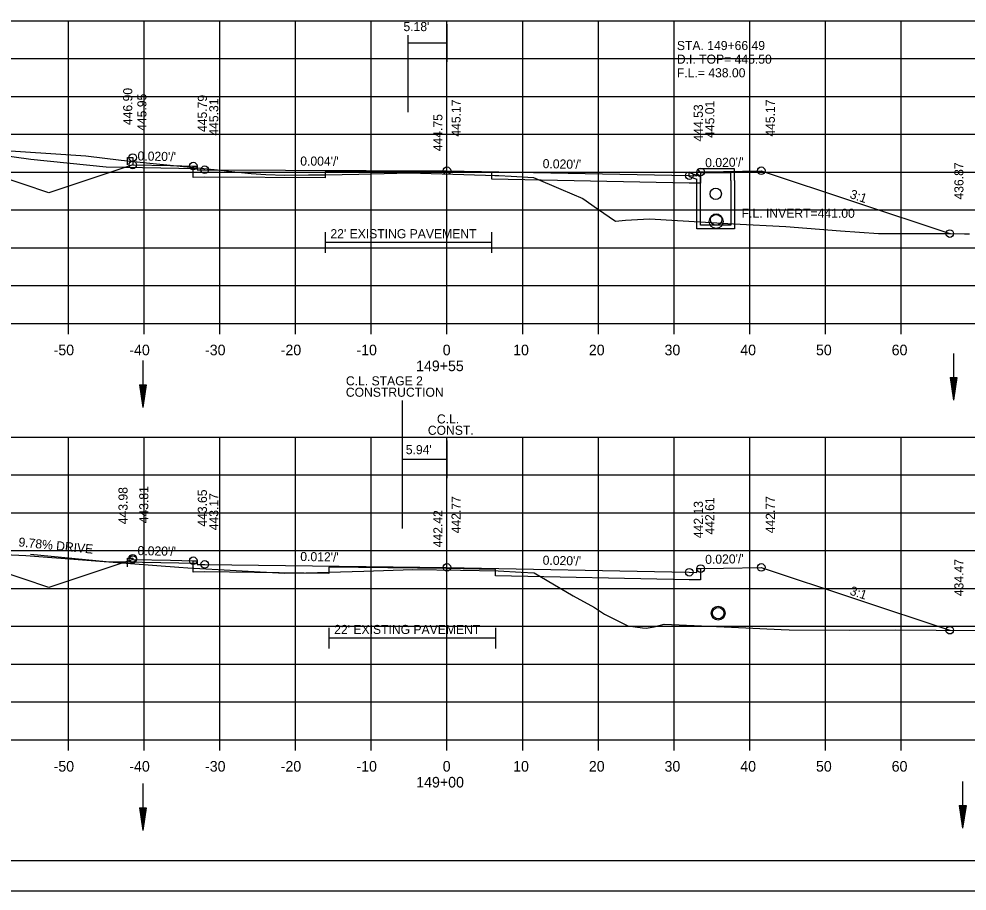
# Model space of a CAD drawing. Extents: x 1538688 to 1540766, y 656250 to 671912.
# Drawn here: x 1538801.6 to 1538926.9, y 664444.7 to 664559.9 of the extents above; entities that cross this region are included whole.
import ezdxf

# ---------------------------------------------------------------- set-up
doc = ezdxf.new("R2010")
doc.units = 0
for name, color, linetype in [('15', 7, 'Continuous'), ('16', 7, 'Continuous'), ('18', 7, 'Continuous'), ('20', 7, 'Continuous'), ('22', 7, 'Continuous'), ('26', 7, 'Continuous'), ('39', 7, 'Continuous'), ('40', 7, 'Continuous'), ('41', 7, 'Continuous'), ('42', 7, 'Continuous'), ('7', 7, 'Continuous'), ('Borings', 7, 'Continuous'), ('Default', 7, 'Continuous'), ('Horizontal Alignment', 7, 'Continuous'), ('RipRap', 7, 'Continuous'), ('Wall Heights', 7, 'Continuous')]:
    doc.layers.add(name, color=color, linetype=linetype)

msp = doc.modelspace()

# ---------------------------------------------------------------- linework, layer by layer
at = {"layer": '15'}
for p, q in [((1538924.64, 664512.58), (1538925.09, 664509.58)), ((1538924.64, 664512.58), (1538925.54, 664512.58)), ((1538924.71, 664512.58), (1538925.09, 664510.08)), ((1538924.79, 664512.58), (1538925.09, 664510.6)), ((1538924.86, 664512.58), (1538925.09, 664511.1)), ((1538924.94, 664512.58), (1538925.09, 664511.61)), ((1538925.01, 664512.58), (1538925.09, 664512.11)), ((1538925.54, 664512.58), (1538925.09, 664509.58)), ((1538925.23, 664512.58), (1538925.09, 664511.61)), ((1538925.38, 664512.58), (1538925.09, 664510.6)), ((1538925.46, 664512.58), (1538925.09, 664510.08)), ((1538925.31, 664512.58), (1538925.09, 664511.1)), ((1538925.16, 664512.58), (1538925.09, 664512.11)), ((1538817.56, 664511.63), (1538818.01, 664508.63)), ((1538817.56, 664511.63), (1538818.46, 664511.63)), ((1538817.64, 664511.63), (1538818.01, 664509.13)), ((1538817.71, 664511.63), (1538818.01, 664509.65)), ((1538817.79, 664511.63), (1538818.01, 664510.15)), ((1538817.87, 664511.63), (1538818.01, 664510.66)), ((1538817.94, 664511.63), (1538818.01, 664511.16)), ((1538818.46, 664511.63), (1538818.01, 664508.63)), ((1538818.16, 664511.63), (1538818.01, 664510.66)), ((1538818.31, 664511.63), (1538818.01, 664509.65)), ((1538818.39, 664511.63), (1538818.01, 664509.13)), ((1538818.23, 664511.63), (1538818.01, 664510.15)), ((1538818.08, 664511.63), (1538818.01, 664511.16)), ((1538817.56, 664455.75), (1538818.01, 664452.75)), ((1538817.56, 664455.75), (1538818.46, 664455.75)), ((1538817.64, 664455.75), (1538818.01, 664453.25)), ((1538817.71, 664455.75), (1538818.01, 664453.77)), ((1538817.79, 664455.75), (1538818.01, 664454.26)), ((1538817.87, 664455.75), (1538818.01, 664454.77)), ((1538817.94, 664455.75), (1538818.01, 664455.27)), ((1538818.46, 664455.75), (1538818.01, 664452.75)), ((1538818.16, 664455.75), (1538818.01, 664454.77)), ((1538818.31, 664455.75), (1538818.01, 664453.77)), ((1538818.39, 664455.75), (1538818.01, 664453.25)), ((1538818.23, 664455.75), (1538818.01, 664454.26)), ((1538818.08, 664455.75), (1538818.01, 664455.27)), ((1538925.84, 664456.03), (1538926.29, 664453.03)), ((1538925.84, 664456.03), (1538926.74, 664456.03)), ((1538925.91, 664456.03), (1538926.29, 664453.53)), ((1538925.99, 664456.03), (1538926.29, 664454.05)), ((1538926.06, 664456.03), (1538926.29, 664454.55)), ((1538926.14, 664456.03), (1538926.29, 664455.06)), ((1538926.22, 664456.03), (1538926.29, 664455.56)), ((1538926.74, 664456.03), (1538926.29, 664453.03)), ((1538926.43, 664456.03), (1538926.29, 664455.06)), ((1538926.59, 664456.03), (1538926.29, 664454.05)), ((1538926.66, 664456.03), (1538926.29, 664453.53)), ((1538926.51, 664456.03), (1538926.29, 664454.55)), ((1538926.36, 664456.03), (1538926.29, 664455.56))]:
    msp.add_line(p, q, dxfattribs=at)
at = {"layer": '16'}
for p, q in [((1538790.74, 664543.18), (1538803.23, 664541.42)), ((1538803.23, 664541.42), (1538813.18, 664540.42)), ((1538813.18, 664540.42), (1538825.18, 664540.18)), ((1538803.19, 664489.26), (1538813.18, 664488.29)), ((1538813.18, 664488.29), (1538825.18, 664488.05))]:
    msp.add_line(p, q, dxfattribs=at)
at = {"layer": '18'}
for points in [[(1538797.82, 664542.7), (1538810.49, 664541.85), (1538815.14, 664541.28), (1538818.91, 664540.9), (1538828.75, 664539.92), (1538829.31, 664539.86), (1538832.32, 664539.52), (1538834.25, 664539.4), (1538836.77, 664539.3), (1538839.91, 664539.34), (1538842.14, 664539.34), (1538846.55, 664539.44), (1538853.25, 664539.61), (1538863.26, 664539.32), (1538864.5, 664539.29), (1538865.02, 664539.27), (1538866.66, 664539.17), (1538869.6, 664539.01), (1538873.2, 664537.48), (1538876.12, 664536.21), (1538878.06, 664534.88), (1538880.43, 664533.24), (1538881.76, 664533.35), (1538884.92, 664533.56), (1538896.03, 664532.89), (1538902.95, 664532.55), (1538910.17, 664531.98), (1538915.19, 664531.62), (1538924.68, 664531.59), (1538926.55, 664531.56), (1538927.22, 664531.57)], [(1538794.05, 664489.47), (1538802.56, 664489.07), (1538816.95, 664487.98), (1538822.75, 664487.53), (1538823.96, 664487.46), (1538836.74, 664486.73), (1538839.54, 664486.76), (1538842.57, 664486.85), (1538847.2, 664487.01), (1538853.67, 664487.22), (1538859.98, 664487.12), (1538864.94, 664487.03), (1538867.96, 664486.86), (1538869.69, 664486.79), (1538874.83, 664483.72), (1538877.68, 664482.19), (1538878.97, 664481.33), (1538882.09, 664479.77), (1538884, 664479.51), (1538884.49, 664479.45), (1538885.56, 664479.66), (1538886.89, 664480), (1538895.77, 664479.62), (1538902.31, 664479.29), (1538903.37, 664479.27), (1538911.34, 664479.21), (1538917.4, 664479.26), (1538922.81, 664479.21), (1538931.33, 664479.15)]]:
    msp.add_lwpolyline(points, dxfattribs=at)
at = {"layer": '20'}
for points in [[(1538815.99, 664540.67), (1538816, 664541.63), (1538816.67, 664541.63), (1538816.68, 664541.13), (1538816.68, 664540.67), (1538821.67, 664540.57), (1538824.67, 664540.51), (1538825.17, 664540.51), (1538825.18, 664540.01), (1538826.18, 664540.03), (1538858.18, 664539.9), (1538890.18, 664539.26), (1538891.18, 664539.24), (1538891.19, 664539.74), (1538891.69, 664539.74), (1538894.69, 664539.8), (1538899.69, 664539.9), (1538924.6, 664531.59)], [(1538815.99, 664487.56), (1538816, 664488.31), (1538816, 664488.7), (1538816.67, 664488.7), (1538816.68, 664488.54), (1538821.67, 664488.44), (1538824.67, 664488.38), (1538825.17, 664488.38), (1538825.18, 664487.88), (1538826.18, 664487.9), (1538858.18, 664487.5), (1538890.18, 664486.86), (1538891.18, 664486.84), (1538891.19, 664487.34), (1538891.69, 664487.34), (1538894.69, 664487.4), (1538899.69, 664487.5), (1538924.6, 664479.2)]]:
    msp.add_lwpolyline(points, dxfattribs=at)
at = {"layer": '22'}
for p, q in [((1538718.18, 664559.72), (1538998.18, 664559.72)), ((1538808.18, 664519.72), (1538808.18, 664559.72)), ((1538818.18, 664519.72), (1538818.18, 664559.72)), ((1538828.18, 664519.72), (1538828.18, 664559.72)), ((1538838.18, 664519.72), (1538838.18, 664559.72)), ((1538848.18, 664519.72), (1538848.18, 664559.72)), ((1538858.18, 664519.72), (1538858.18, 664559.72)), ((1538868.18, 664519.72), (1538868.18, 664559.72)), ((1538878.18, 664519.72), (1538878.18, 664559.72)), ((1538888.18, 664519.72), (1538888.18, 664559.72)), ((1538898.18, 664519.72), (1538898.18, 664559.72)), ((1538908.18, 664519.72), (1538908.18, 664559.72)), ((1538918.18, 664519.72), (1538918.18, 664559.72)), ((1538718.18, 664554.72), (1538998.18, 664554.72)), ((1538718.18, 664549.72), (1538998.18, 664549.72)), ((1538718.18, 664544.72), (1538998.18, 664544.72)), ((1538718.18, 664539.72), (1538998.18, 664539.72)), ((1538718.18, 664534.72), (1538998.18, 664534.72)), ((1538718.18, 664529.72), (1538998.18, 664529.72)), ((1538718.18, 664524.72), (1538998.18, 664524.72)), ((1538718.18, 664519.72), (1538998.18, 664519.72)), ((1538718.18, 664504.72), (1538998.18, 664504.72)), ((1538808.18, 664464.72), (1538808.18, 664504.72)), ((1538818.18, 664464.72), (1538818.18, 664504.72)), ((1538828.18, 664464.72), (1538828.18, 664504.72)), ((1538838.18, 664464.72), (1538838.18, 664504.72)), ((1538848.18, 664464.72), (1538848.18, 664504.72)), ((1538858.18, 664464.72), (1538858.18, 664504.72)), ((1538868.18, 664464.72), (1538868.18, 664504.72)), ((1538878.18, 664464.72), (1538878.18, 664504.72)), ((1538888.18, 664464.72), (1538888.18, 664504.72)), ((1538898.18, 664464.72), (1538898.18, 664504.72)), ((1538908.18, 664464.72), (1538908.18, 664504.72)), ((1538918.18, 664464.72), (1538918.18, 664504.72)), ((1538718.18, 664499.72), (1538998.18, 664499.72)), ((1538718.18, 664494.72), (1538998.18, 664494.72)), ((1538718.18, 664489.72), (1538998.18, 664489.72)), ((1538718.18, 664484.72), (1538998.18, 664484.72)), ((1538718.18, 664479.72), (1538998.18, 664479.72)), ((1538718.18, 664474.72), (1538998.18, 664474.72)), ((1538718.18, 664469.72), (1538998.18, 664469.72)), ((1538718.18, 664464.72), (1538998.18, 664464.72))]:
    msp.add_line(p, q, dxfattribs=at)
at = {"layer": '26'}
msp.add_line((1538687.78, 664444.75), (1539021.11, 664444.75), dxfattribs=at)
msp.add_lwpolyline([(1538687.77, 664658.08), (1539021.11, 664658.08), (1539021.11, 664444.74), (1538687.77, 664444.74)], close=True, dxfattribs=at)
for centre, radius in [((1538816.67, 664541.63), 0.5), ((1538816.68, 664540.67), 0.5), ((1538824.67, 664540.51), 0.5), ((1538826.18, 664540.03), 0.5), ((1538858.18, 664539.9), 0.5), ((1538890.18, 664539.26), 0.5), ((1538891.69, 664539.74), 0.5), ((1538899.69, 664539.9), 0.5), ((1538893.73, 664533.18), 0.917), ((1538924.6, 664531.59), 0.5), ((1538816.67, 664488.7), 0.5), ((1538816.68, 664488.54), 0.5), ((1538824.67, 664488.38), 0.5), ((1538826.18, 664487.9), 0.5), ((1538858.18, 664487.5), 0.5), ((1538890.18, 664486.86), 0.5), ((1538891.69, 664487.34), 0.5), ((1538899.69, 664487.5), 0.5), ((1538894.01, 664481.45), 0.917), ((1538924.6, 664479.2), 0.5)]:
    msp.add_circle(centre, radius, dxfattribs=at)
at = {"layer": '39'}
for p, q in [((1538890.18, 664539.65), (1538891.68, 664539.13)), ((1538891.34, 664539.97), (1538891.43, 664540.13)), ((1538891.34, 664539.97), (1538891.68, 664539.63)), ((1538896.18, 664540.13), (1538891.43, 664540.13)), ((1538895.68, 664539.63), (1538891.68, 664539.63)), ((1538895.68, 664538.63), (1538895.68, 664539.63)), ((1538896.18, 664538.63), (1538896.18, 664540.13)), ((1538890.18, 664539.13), (1538891.18, 664538.78)), ((1538891.18, 664538.63), (1538891.18, 664538.78)), ((1538891.68, 664538.63), (1538891.68, 664539.13)), ((1538925.09, 664515.77), (1538925.09, 664509.58)), ((1538818.01, 664514.82), (1538818.01, 664508.63)), ((1538818.01, 664458.94), (1538818.01, 664452.75)), ((1538926.29, 664459.22), (1538926.29, 664453.03))]:
    msp.add_line(p, q, dxfattribs=at)
for points in [[(1538890.18, 664539.13), (1538890.18, 664539.65)], [(1538896.18, 664538.63), (1538896.18, 664532.22), (1538893.68, 664532.22), (1538891.18, 664532.22), (1538891.18, 664538.63)], [(1538895.68, 664538.63), (1538895.68, 664532.72), (1538893.68, 664532.72), (1538891.68, 664532.72), (1538891.68, 664538.63)]]:
    msp.add_lwpolyline(points, dxfattribs=at)
for centre in [(1538893.68, 664536.85), (1538893.74, 664533.46), (1538894.01, 664481.45)]:
    msp.add_circle(centre, 0.75, dxfattribs=at)
at = {"layer": '7'}
for p, q in [((1538842.08, 664531.79), (1538842.08, 664529.04)), ((1538864.08, 664531.79), (1538864.08, 664529.04)), ((1538864.08, 664530.42), (1538842.08, 664530.42)), ((1538842.58, 664479.52), (1538842.58, 664476.77)), ((1538864.58, 664479.52), (1538864.58, 664476.77)), ((1538864.58, 664478.14), (1538842.58, 664478.14))]:
    msp.add_line(p, q, dxfattribs=at)
at = {"layer": 'Borings'}
for p, q in [((1538718.18, 664519.72), (1538998.18, 664519.72)), ((1538808.18, 664518.32), (1538808.18, 664519.72)), ((1538818.18, 664518.32), (1538818.18, 664519.72)), ((1538828.18, 664518.32), (1538828.18, 664519.72)), ((1538838.18, 664518.32), (1538838.18, 664519.72)), ((1538848.18, 664518.32), (1538848.18, 664519.72)), ((1538858.18, 664518.32), (1538858.18, 664519.72)), ((1538868.18, 664518.32), (1538868.18, 664519.72)), ((1538878.18, 664518.32), (1538878.18, 664519.72)), ((1538888.18, 664518.32), (1538888.18, 664519.72)), ((1538898.18, 664518.32), (1538898.18, 664519.72)), ((1538908.18, 664518.32), (1538908.18, 664519.72)), ((1538918.18, 664518.32), (1538918.18, 664519.72)), ((1538718.18, 664464.72), (1538998.18, 664464.72)), ((1538808.18, 664463.32), (1538808.18, 664464.72)), ((1538818.18, 664463.32), (1538818.18, 664464.72)), ((1538828.18, 664463.32), (1538828.18, 664464.72)), ((1538838.18, 664463.32), (1538838.18, 664464.72)), ((1538848.18, 664463.32), (1538848.18, 664464.72)), ((1538858.18, 664463.32), (1538858.18, 664464.72)), ((1538868.18, 664463.32), (1538868.18, 664464.72)), ((1538878.18, 664463.32), (1538878.18, 664464.72)), ((1538888.18, 664463.32), (1538888.18, 664464.72)), ((1538898.18, 664463.32), (1538898.18, 664464.72)), ((1538908.18, 664463.32), (1538908.18, 664464.72)), ((1538918.18, 664463.32), (1538918.18, 664464.72))]:
    msp.add_line(p, q, dxfattribs=at)
at = {"layer": 'Default'}
for p, q in [((1538858.18, 664559.27), (1538858.18, 664554.27)), ((1538853, 664557.83), (1538853, 664547.65)), ((1538858.18, 664556.77), (1538853, 664556.77)), ((1538852.24, 664509.56), (1538852.24, 664492.65)), ((1538858.18, 664504.27), (1538858.18, 664499.27)), ((1538858.18, 664501.77), (1538852.24, 664501.77))]:
    msp.add_line(p, q, dxfattribs=at)
at = {"layer": 'RipRap'}
for p, q in [((1538805.59, 664536.98), (1538797.38, 664539.72)), ((1538816.68, 664540.67), (1538805.59, 664536.98)), ((1538816.68, 664488.54), (1538805.59, 664484.84)), ((1538805.59, 664484.84), (1538797.38, 664487.58)), ((1539016.36, 664448.72), (1538700.18, 664448.72))]:
    msp.add_line(p, q, dxfattribs=at)
at = {"layer": 'Wall Heights'}
for points in [[(1538891.69, 664539.74), (1538891.69, 664538.24), (1538890.18, 664538.26), (1538864.09, 664538.78), (1538864.09, 664539.61), (1538858.18, 664539.73), (1538842.09, 664539.8), (1538842.09, 664538.97), (1538826.18, 664539.03), (1538824.67, 664539.01), (1538824.67, 664540.51)], [(1538891.69, 664487.34), (1538891.69, 664485.84), (1538890.18, 664485.86), (1538864.59, 664486.37), (1538864.59, 664487.2), (1538858.18, 664487.33), (1538842.59, 664487.53), (1538842.59, 664486.7), (1538826.18, 664486.9), (1538824.67, 664486.88), (1538824.67, 664488.38)]]:
    msp.add_lwpolyline(points, dxfattribs=at)

# ---------------------------------------------------------------- texts
at = {"layer": '16'}
msp.add_text('9.78% DRIVE', height=1.2, rotation=354.4166, dxfattribs=at).set_placement((1538801.54, 664490.27))
at = {"layer": '40'}
for s, p in [('STA. 149+66.49', (1538888.55, 664555.84)), ('D.I. TOP= 445.50', (1538888.55, 664554.04)), ('F.L.= 438.00', (1538888.55, 664552.24)), ('F.L. INVERT=441.00', (1538897.11, 664533.68))]:
    msp.add_text(s, height=1.2, dxfattribs=at).set_placement(p)
at = {"layer": '41'}
for s, p in [('446.90', (1538816.61, 664545.93)), ('445.95', (1538818.48, 664545.17)), ('445.79', (1538826.47, 664545.01)), ('445.31', (1538827.98, 664544.53)), ('445.17', (1538859.98, 664544.4)), ('444.53', (1538891.98, 664543.76)), ('445.01', (1538893.49, 664544.24)), ('445.17', (1538901.49, 664544.4)), ('444.75', (1538857.58, 664542.47)), ('436.87', (1538926.4, 664536.09)), ('443.98', (1538815.99, 664493.2)), ('443.81', (1538818.73, 664493.32)), ('443.65', (1538826.47, 664492.88)), ('443.17', (1538827.98, 664492.4)), ('442.77', (1538859.98, 664492)), ('442.13', (1538891.98, 664491.36)), ('442.61', (1538893.49, 664491.84)), ('442.77', (1538901.49, 664492)), ('442.42', (1538857.58, 664490.15)), ('434.47', (1538926.4, 664483.7))]:
    msp.add_text(s, height=1.2, rotation=90, dxfattribs=at).set_placement(p)
at = {"layer": '42'}
for s, rotation, p in [("0.020'/'", 358.8542, (1538817.3, 664541.26)), ("0.004'/'", 359.7529, (1538838.8, 664540.58)), ("0.020'/'", 358.8542, (1538870.81, 664540.24)), ("0.020'/'", 1.1458, (1538892.3, 664540.35)), ('3:1', 341.5651, (1538911.3, 664536.32)), ("0.020'/'", 358.8542, (1538817.3, 664489.12)), ("0.012'/'", 359.2861, (1538838.8, 664488.34)), ("0.020'/'", 358.8542, (1538870.81, 664487.85)), ("0.020'/'", 1.1458, (1538892.3, 664487.95)), ('3:1', 341.5651, (1538911.3, 664483.92))]:
    msp.add_text(s, height=1.2, rotation=rotation, dxfattribs=at).set_placement(p)
at = {"layer": '7'}
for p in [(1538842.78, 664530.98), (1538843.28, 664478.7)]:
    msp.add_text("22' EXISTING PAVEMENT", height=1.2, dxfattribs=at).set_placement(p)
at = {"layer": 'Default'}
for s, p in [("5.18'", (1538852.43, 664558.34)), ('C.L. STAGE 2', (1538844.83, 664511.54)), ('CONSTRUCTION', (1538844.82, 664510.04)), ('C.L.', (1538856.85, 664506.51)), ('CONST.', (1538855.65, 664505.01)), ("5.94'", (1538852.74, 664502.45))]:
    msp.add_text(s, height=1.2, dxfattribs=at).set_placement(p)
at = {"layer": 'Horizontal Alignment'}
for s, p in [('-50', (1538806.22, 664515.52)), ('-40', (1538816.22, 664515.52)), ('-30', (1538826.22, 664515.52)), ('-20', (1538836.22, 664515.52)), ('-10', (1538846.22, 664515.52)), ('0', (1538857.62, 664515.52)), ('10', (1538866.92, 664515.52)), ('20', (1538876.92, 664515.52)), ('30', (1538886.92, 664515.52)), ('40', (1538896.92, 664515.52)), ('50', (1538906.92, 664515.52)), ('60', (1538916.92, 664515.52)), ('149+55', (1538854.1, 664513.42)), ('-50', (1538806.22, 664460.52)), ('-40', (1538816.22, 664460.52)), ('-30', (1538826.22, 664460.52)), ('-20', (1538836.22, 664460.52)), ('-10', (1538846.22, 664460.52)), ('0', (1538857.62, 664460.52)), ('10', (1538866.92, 664460.52)), ('20', (1538876.92, 664460.52)), ('30', (1538886.92, 664460.52)), ('40', (1538896.92, 664460.52)), ('50', (1538906.92, 664460.52)), ('60', (1538916.92, 664460.52)), ('149+00', (1538854.12, 664458.42))]:
    msp.add_text(s, height=1.4, dxfattribs=at).set_placement(p)

doc.saveas('drawing.dxf')
